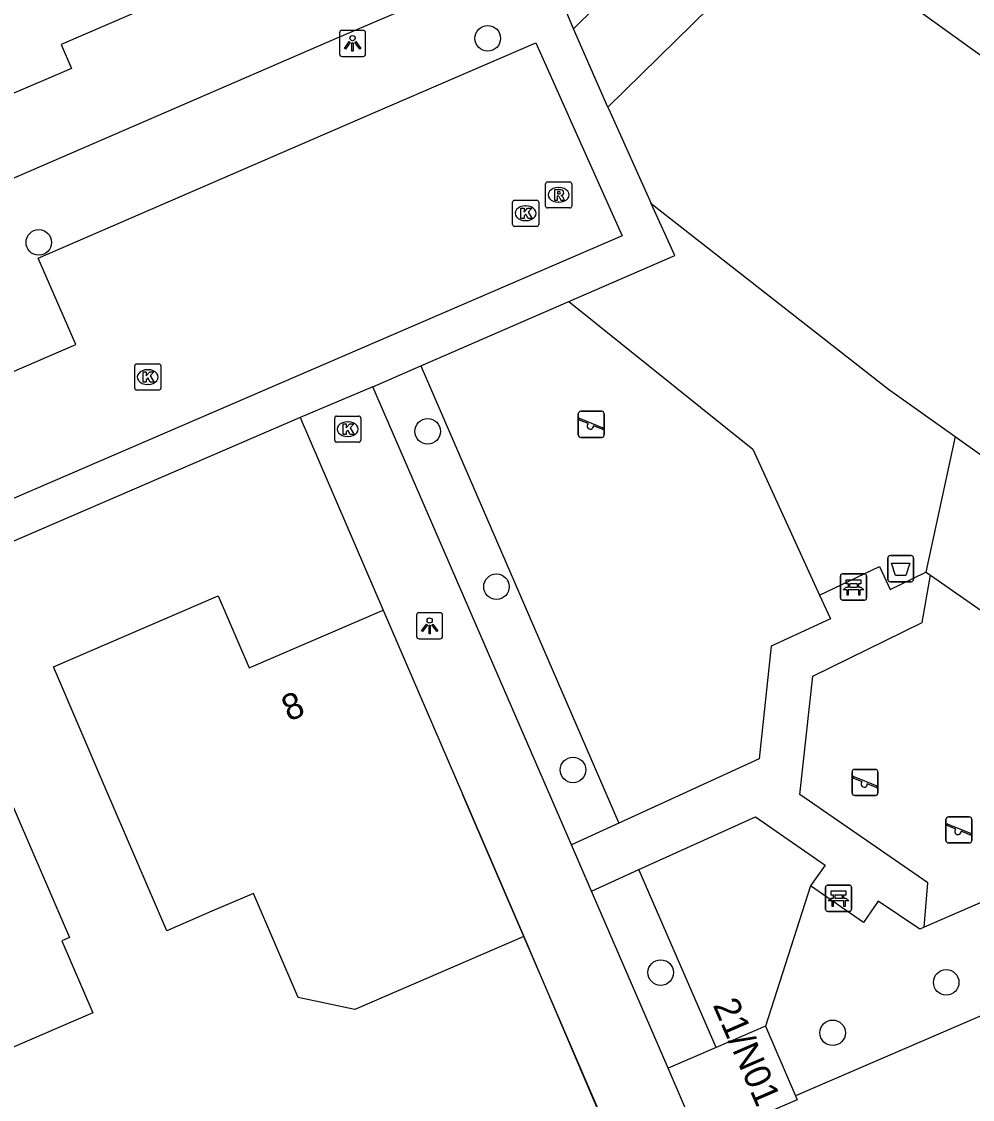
# Model space of a CAD drawing. Extents: x 157767 to 159171, y 387842 to 389425.
# Drawn here: x 158188.84 to 158225.26, y 388712.22 to 388753.46 of the extents above; entities that cross this region are included whole.
import ezdxf

# ---------------------------------------------------------------- set-up
doc = ezdxf.new("R2010")
doc.units = 0
for name, color, linetype in [('IMGEO_Afvalbak', 7, 'Continuous'), ('IMGEO_Bank', 7, 'Continuous'), ('IMGEO_Boom', 7, 'Continuous'), ('IMGEO_Groenvoorziening', 7, 'Continuous'), ('IMGEO_Kolk', 7, 'Continuous'), ('IMGEO_Lichtpunt', 7, 'Continuous'), ('IMGEO_Muur', 7, 'Continuous'), ('IMGEO_Pand', 7, 'Continuous'), ('IMGEO_Pand_nummerreeks', 7, 'Continuous'), ('IMGEO_Rijbaan_lokaal_open', 7, 'Continuous'), ('IMGEO_Rioolput', 7, 'Continuous'), ('IMGEO_Speelvoorziening', 7, 'Continuous'), ('IMGEO_Voetpad_open', 7, 'Continuous')]:
    doc.layers.add(name, color=color, linetype=linetype)

msp = doc.modelspace()

# ---------------------------------------------------------------- linework, layer by layer
at = {"layer": 'IMGEO_Afvalbak'}
for p, q in [((158222.016, 388732.127), (158222.016, 388732.927)), ((158222.016, 388732.927), (158222.016, 388732.127)), ((158222.116, 388733.027), (158222.906, 388733.027)), ((158222.906, 388733.027), (158222.116, 388733.027)), ((158223.006, 388732.927), (158223.006, 388732.127)), ((158223.006, 388732.127), (158223.006, 388732.927)), ((158222.906, 388732.027), (158222.116, 388732.027)), ((158222.116, 388732.027), (158222.906, 388732.027))]:
    msp.add_line(p, q, dxfattribs=at)
msp.add_lwpolyline([(158222.159, 388732.741), (158222.863, 388732.741), (158222.714, 388732.271), (158222.308, 388732.271), (158222.159, 388732.741)], dxfattribs=at)
for centre, start, end in [((158222.116, 388732.927), 90, 180), ((158222.116, 388732.927), 90, 180), ((158222.906, 388732.927), 0, 90), ((158222.906, 388732.927), 360, 90), ((158222.116, 388732.127), 180, 270), ((158222.116, 388732.127), 180, 270), ((158222.906, 388732.127), 270, 0), ((158222.906, 388732.127), 270, 0)]:
    msp.add_arc(centre, 0.1, start, end, dxfattribs=at)
at = {"layer": 'IMGEO_Bank'}
for p, q in [((158220.204, 388731.4), (158220.204, 388732.241)), ((158220.204, 388732.241), (158220.204, 388731.4)), ((158220.279, 388732.325), (158221.12, 388732.325)), ((158221.12, 388732.325), (158220.279, 388732.325)), ((158221.204, 388732.25), (158221.204, 388731.409)), ((158221.204, 388731.409), (158221.204, 388732.25)), ((158220.901, 388731.723), (158220.508, 388731.723)), ((158220.513, 388731.831), (158220.513, 388731.937)), ((158220.557, 388731.937), (158220.557, 388731.831)), ((158220.845, 388731.943), (158220.563, 388731.943)), ((158220.563, 388731.825), (158220.845, 388731.825)), ((158220.851, 388731.831), (158220.851, 388731.937)), ((158220.895, 388731.937), (158220.895, 388731.831)), ((158221.129, 388731.325), (158220.288, 388731.325)), ((158220.288, 388731.325), (158221.129, 388731.325)), ((158219.632, 388719.489), (158219.632, 388720.33)), ((158219.632, 388720.33), (158219.632, 388719.489)), ((158219.707, 388720.414), (158220.548, 388720.414)), ((158220.548, 388720.414), (158219.707, 388720.414)), ((158220.632, 388720.339), (158220.632, 388719.498)), ((158220.632, 388719.498), (158220.632, 388720.339)), ((158220.329, 388719.812), (158219.936, 388719.812)), ((158219.941, 388719.92), (158219.941, 388720.026)), ((158219.985, 388720.026), (158219.985, 388719.92)), ((158220.273, 388720.032), (158219.991, 388720.032)), ((158219.991, 388719.914), (158220.273, 388719.914)), ((158220.279, 388719.92), (158220.279, 388720.026)), ((158220.323, 388720.026), (158220.323, 388719.92)), ((158220.557, 388719.414), (158219.716, 388719.414)), ((158219.716, 388719.414), (158220.557, 388719.414))]:
    msp.add_line(p, q, dxfattribs=at)
for points in [[(158220.507, 388731.943), (158220.421, 388731.943), (158220.421, 388732.104), (158220.984, 388732.104), (158220.984, 388731.943), (158220.901, 388731.943)], [(158220.451, 388731.723), (158220.309, 388731.723), (158220.421, 388731.825), (158220.507, 388731.825)], [(158220.501, 388731.716), (158220.501, 388731.509), (158220.458, 388731.509), (158220.458, 388731.716)], [(158220.901, 388731.825), (158220.984, 388731.825), (158221.096, 388731.723), (158220.957, 388731.723)], [(158220.951, 388731.716), (158220.951, 388731.509), (158220.907, 388731.509), (158220.907, 388731.716)], [(158219.935, 388720.032), (158219.849, 388720.032), (158219.849, 388720.193), (158220.412, 388720.193), (158220.412, 388720.032), (158220.329, 388720.032)], [(158219.879, 388719.812), (158219.737, 388719.812), (158219.849, 388719.914), (158219.935, 388719.914)], [(158219.929, 388719.805), (158219.929, 388719.598), (158219.886, 388719.598), (158219.886, 388719.805)], [(158220.329, 388719.914), (158220.412, 388719.914), (158220.524, 388719.812), (158220.385, 388719.812)], [(158220.379, 388719.805), (158220.379, 388719.598), (158220.335, 388719.598), (158220.335, 388719.805)]]:
    msp.add_lwpolyline(points, dxfattribs=at)
for centre, radius, start, end in [((158220.282, 388732.247), 0.0779, 92.4484, 184.2845), ((158220.282, 388732.247), 0.0779, 92.4484, 184.2845), ((158221.126, 388732.247), 0.0779, 2.4484, 94.2845), ((158221.126, 388732.247), 0.0779, 2.4484, 94.2845), ((158220.451, 388731.716), 0.00671, 2.8957, 87.1043), ((158220.508, 388731.716), 0.00671, 92.8957, 177.1043), ((158220.506, 388731.936), 0.00671, 2.8957, 87.1043), ((158220.506, 388731.832), 0.00671, 272.8957, 357.1043), ((158220.563, 388731.936), 0.00671, 92.8957, 177.1043), ((158220.563, 388731.832), 0.00671, 182.8957, 267.1043), ((158220.845, 388731.936), 0.00671, 2.8957, 87.1043), ((158220.845, 388731.832), 0.00671, 272.8957, 357.1043), ((158220.902, 388731.936), 0.00671, 92.8957, 177.1043), ((158220.902, 388731.832), 0.00671, 182.8957, 267.1043), ((158220.9, 388731.716), 0.00671, 2.8957, 87.1043), ((158220.957, 388731.716), 0.00671, 92.8957, 177.1043), ((158220.282, 388731.403), 0.0779, 182.4484, 274.2845), ((158220.282, 388731.403), 0.0779, 182.4484, 274.2845), ((158221.126, 388731.403), 0.0779, 272.4484, 4.2845), ((158221.126, 388731.403), 0.0779, 272.4484, 4.2845), ((158219.71, 388720.336), 0.0779, 92.4484, 184.2845), ((158219.71, 388720.336), 0.0779, 92.4484, 184.2845), ((158220.554, 388720.336), 0.0779, 2.4484, 94.2845), ((158220.554, 388720.336), 0.0779, 2.4484, 94.2845), ((158219.879, 388719.805), 0.00671, 2.8957, 87.1043), ((158219.936, 388719.805), 0.00671, 92.8957, 177.1043), ((158219.934, 388720.025), 0.00671, 2.8957, 87.1043), ((158219.934, 388719.921), 0.00671, 272.8957, 357.1043), ((158219.991, 388720.025), 0.00671, 92.8957, 177.1043), ((158219.991, 388719.921), 0.00671, 182.8957, 267.1043), ((158220.273, 388720.025), 0.00671, 2.8957, 87.1043), ((158220.273, 388719.921), 0.00671, 272.8957, 357.1043), ((158220.33, 388720.025), 0.00671, 92.8957, 177.1043), ((158220.33, 388719.921), 0.00671, 182.8957, 267.1043), ((158220.328, 388719.805), 0.00671, 2.8957, 87.1043), ((158220.385, 388719.805), 0.00671, 92.8957, 177.1043), ((158219.71, 388719.492), 0.0779, 182.4484, 274.2845), ((158219.71, 388719.492), 0.0779, 182.4484, 274.2845), ((158220.554, 388719.492), 0.0779, 272.4484, 4.2845), ((158220.554, 388719.492), 0.0779, 272.4484, 4.2845)]:
    msp.add_arc(centre, radius, start, end, dxfattribs=at)
at = {"layer": 'IMGEO_Boom'}
for centre in [(158206.697, 388752.822), (158189.504, 388745.012), (158204.397, 388737.783), (158207.03, 388731.836), (158209.962, 388724.825), (158213.321, 388717.071), (158224.255, 388716.695), (158219.903, 388714.766)]:
    msp.add_circle(centre, 0.489, dxfattribs=at)
at = {"layer": 'IMGEO_Groenvoorziening'}
for points in [[(158212.961, 388746.496), (158222.043, 388739.397), (158224.591, 388737.583)], [(158209.8, 388742.746), (158216.855, 388737.107), (158219.408, 388731.518)], [(158204.129, 388740.284), (158211.717, 388722.785)], [(158224.591, 388737.583), (158223.475, 388732.398)], [(158224.591, 388737.583), (158233.388, 388731.323)], [(158223.652, 388732.275), (158230.525, 388727.497)], [(158233.388, 388731.323), (158243.682, 388723.997), (158242.224, 388722.582), (158218.48, 388712.357)], [(158230.525, 388727.497), (158229.878, 388721.619), (158223.408, 388718.812)], [(158215.439, 388714.205), (158212.486, 388721.014)], [(158219.055, 388720.384), (158217.333, 388715.021)]]:
    msp.add_lwpolyline(points, dxfattribs=at)
at = {"layer": 'IMGEO_Kolk'}
for p, q in [((158207.648, 388745.701), (158207.648, 388746.553)), ((158207.723, 388746.627), (158208.575, 388746.627)), ((158208.649, 388746.553), (158208.649, 388745.701)), ((158208.136, 388746.407), (158208.161, 388746.407)), ((158208.159, 388745.847), (158208.134, 388745.847)), ((158208.575, 388745.627), (158207.723, 388745.627)), ((158193.251, 388740.361), (158194.103, 388740.361)), ((158193.176, 388739.435), (158193.176, 388740.287)), ((158193.664, 388740.141), (158193.689, 388740.141)), ((158194.177, 388740.287), (158194.177, 388739.435)), ((158193.687, 388739.581), (158193.662, 388739.581)), ((158194.103, 388739.361), (158193.251, 388739.361)), ((158200.835, 388737.441), (158200.835, 388738.293)), ((158200.91, 388738.367), (158201.762, 388738.367)), ((158201.836, 388738.293), (158201.836, 388737.441)), ((158201.323, 388738.147), (158201.348, 388738.147)), ((158201.346, 388737.587), (158201.321, 388737.587)), ((158201.762, 388737.367), (158200.91, 388737.367))]:
    msp.add_line(p, q, dxfattribs=at)
for points in [[(158207.648, 388745.701), (158207.648, 388746.553)], [(158207.723, 388746.627), (158208.575, 388746.627)], [(158208.649, 388746.553), (158208.649, 388745.701)], [(158207.969, 388746.327), (158208.092, 388746.327), (158208.092, 388746.176), (158208.222, 388746.327), (158208.386, 388746.327), (158208.24, 388746.176), (158208.393, 388745.927), (158208.241, 388745.927), (158208.156, 388746.091), (158208.092, 388746.024), (158208.092, 388745.927), (158207.969, 388745.927), (158207.969, 388746.327)], [(158208.575, 388745.627), (158207.723, 388745.627)], [(158193.251, 388740.361), (158194.103, 388740.361)], [(158193.176, 388739.435), (158193.176, 388740.287)], [(158193.497, 388740.061), (158193.62, 388740.061), (158193.62, 388739.91), (158193.75, 388740.061), (158193.914, 388740.061), (158193.768, 388739.91), (158193.921, 388739.661), (158193.769, 388739.661), (158193.684, 388739.825), (158193.62, 388739.758), (158193.62, 388739.661), (158193.497, 388739.661), (158193.497, 388740.061)], [(158194.177, 388740.287), (158194.177, 388739.435)], [(158194.103, 388739.361), (158193.251, 388739.361)], [(158200.835, 388737.441), (158200.835, 388738.293)], [(158200.91, 388738.367), (158201.762, 388738.367)], [(158201.836, 388738.293), (158201.836, 388737.441)], [(158201.156, 388738.067), (158201.279, 388738.067), (158201.279, 388737.916), (158201.409, 388738.067), (158201.573, 388738.067), (158201.427, 388737.916), (158201.58, 388737.667), (158201.428, 388737.667), (158201.343, 388737.831), (158201.279, 388737.764), (158201.279, 388737.667), (158201.156, 388737.667), (158201.156, 388738.067)], [(158201.762, 388737.367), (158200.91, 388737.367)]]:
    msp.add_lwpolyline(points, dxfattribs=at)
for centre, start, end in [((158207.725, 388746.551), 91.552, 178.448), ((158207.725, 388746.551), 91.552, 178.448), ((158208.573, 388746.551), 1.552, 88.448), ((158208.573, 388746.551), 1.552, 88.448), ((158207.725, 388745.703), 181.552, 268.448), ((158207.725, 388745.703), 181.552, 268.448), ((158208.573, 388745.703), 271.552, 358.448), ((158208.573, 388745.703), 271.552, 358.448), ((158193.253, 388740.285), 91.552, 178.448), ((158193.253, 388740.285), 91.552, 178.448), ((158194.101, 388740.285), 1.552, 88.448), ((158194.101, 388740.285), 1.552, 88.448), ((158193.253, 388739.437), 181.552, 268.448), ((158193.253, 388739.437), 181.552, 268.448), ((158194.101, 388739.437), 271.552, 358.448), ((158194.101, 388739.437), 271.552, 358.448), ((158200.912, 388738.291), 91.552, 178.448), ((158200.912, 388738.291), 91.552, 178.448), ((158201.76, 388738.291), 1.552, 88.448), ((158201.76, 388738.291), 1.552, 88.448), ((158200.912, 388737.443), 181.552, 268.448), ((158200.912, 388737.443), 181.552, 268.448), ((158201.76, 388737.443), 271.552, 358.448), ((158201.76, 388737.443), 271.552, 358.448)]:
    msp.add_arc(centre, 0.0765, start, end, dxfattribs=at)
for centre, major_axis, ratio, start_param, end_param in [((158208.135, 388746.127), (-0.387, 0.002), 0.722429, 4.712389, 7.853982), ((158208.16, 388746.127), (-0.39, 0.002), 0.717154, 1.570796, 4.712389), ((158193.663, 388739.861), (-0.387, 0.002), 0.722429, 4.712389, 7.853982), ((158193.688, 388739.861), (-0.39, 0.002), 0.717154, 1.570796, 4.712389), ((158201.322, 388737.867), (-0.387, 0.002), 0.722429, 4.712389, 7.853982), ((158201.347, 388737.867), (-0.39, 0.002), 0.717154, 1.570796, 4.712389)]:
    msp.add_ellipse(centre, major_axis=major_axis, ratio=ratio, start_param=start_param, end_param=end_param, dxfattribs=at)
at = {"layer": 'IMGEO_Lichtpunt'}
for p, q in [((158201.922, 388753.128), (158201.114, 388753.128)), ((158201.922, 388753.128), (158201.114, 388753.128)), ((158201.02, 388753.033), (158201.02, 388752.226)), ((158201.02, 388753.033), (158201.02, 388752.226)), ((158202.016, 388752.226), (158202.016, 388753.033)), ((158202.016, 388752.226), (158202.016, 388753.033)), ((158201.114, 388752.132), (158201.922, 388752.132)), ((158201.114, 388752.132), (158201.922, 388752.132)), ((158204.875, 388730.841), (158204.067, 388730.841)), ((158204.875, 388730.841), (158204.067, 388730.841)), ((158203.973, 388730.746), (158203.973, 388729.939)), ((158203.973, 388730.746), (158203.973, 388729.939)), ((158204.969, 388729.939), (158204.969, 388730.746)), ((158204.969, 388729.939), (158204.969, 388730.746)), ((158204.067, 388729.845), (158204.875, 388729.845)), ((158204.067, 388729.845), (158204.875, 388729.845))]:
    msp.add_line(p, q, dxfattribs=at)
for points in [[(158201.394, 388752.697), (158201.433, 388752.669), (158201.245, 388752.407), (158201.207, 388752.434), (158201.394, 388752.697)], [(158201.496, 388752.649), (158201.543, 388752.649), (158201.543, 388752.327), (158201.496, 388752.327), (158201.496, 388752.649)], [(158201.606, 388752.669), (158201.644, 388752.696), (158201.831, 388752.434), (158201.792, 388752.406), (158201.606, 388752.669)], [(158204.347, 388730.41), (158204.386, 388730.382), (158204.198, 388730.12), (158204.16, 388730.147), (158204.347, 388730.41)], [(158204.449, 388730.362), (158204.496, 388730.362), (158204.496, 388730.04), (158204.449, 388730.04), (158204.449, 388730.362)], [(158204.559, 388730.382), (158204.597, 388730.409), (158204.784, 388730.147), (158204.745, 388730.119), (158204.559, 388730.382)]]:
    msp.add_lwpolyline(points, dxfattribs=at)
for centre in [(158201.519, 388752.831), (158204.472, 388730.544)]:
    msp.add_circle(centre, 0.0994, dxfattribs=at)
for centre, start, end in [((158201.114, 388753.033), 90, 180), ((158201.114, 388753.033), 90, 180), ((158201.922, 388753.033), 0, 90), ((158201.922, 388753.033), 0, 90), ((158201.114, 388752.226), 180, 270), ((158201.114, 388752.226), 180, 270), ((158201.922, 388752.226), 270, 0), ((158201.922, 388752.226), 270, 360), ((158204.067, 388730.746), 90, 180), ((158204.067, 388730.746), 90, 180), ((158204.875, 388730.746), 0, 90), ((158204.875, 388730.746), 0, 90), ((158204.067, 388729.939), 180, 270), ((158204.067, 388729.939), 180, 270), ((158204.875, 388729.939), 270, 0), ((158204.875, 388729.939), 270, 360)]:
    msp.add_arc(centre, 0.0946, start, end, dxfattribs=at)
at = {"layer": 'IMGEO_Muur'}
msp.add_lwpolyline([(158219.492, 388691.965), (158208.082, 388718.445), (158205.742, 388723.876)], dxfattribs=at)
at = {"layer": 'IMGEO_Pand'}
for points in [[(158185.06, 388764.409), (158190.755, 388766.862), (158194.764, 388761.425), (158197.732, 388757.4), (158193.263, 388755.469), (158193.856, 388754.097), (158190.364, 388752.593), (158190.76, 388751.674), (158188.28, 388750.606), (158187.884, 388751.524), (158186.507, 388750.931), (158184.529, 388755.523), (158182.754, 388759.647), (158180.658, 388758.744), (158178.898, 388762.855), (158184.666, 388765.325), (158185.06, 388764.409)], [(158230.196, 388750.586), (158229.778, 388750), (158228.799, 388748.625), (158228.677, 388748.712), (158226.872, 388750), (158226.022, 388750.606), (158226.604, 388751.421), (158221.686, 388754.973), (158221.107, 388754.172), (158217.789, 388756.568)], [(158208.082, 388718.445), (158201.61, 388715.654), (158199.433, 388716.121), (158197.722, 388720.099), (158196.136, 388719.417), (158194.406, 388718.672), (158192.038, 388724.176), (158190.062, 388728.768), (158196.37, 388731.488), (158197.56, 388728.729), (158202.694, 388730.943)], [(158202.694, 388730.943), (158205.742, 388723.876), (158208.082, 388718.445)], [(158186.531, 388713.361), (158185.717, 388713.645), (158184.761, 388715.865), (158184.222, 388715.633), (158184.064, 388715.999), (158180.256, 388714.358), (158180.611, 388713.534), (158180.336, 388713.416), (158178.45, 388717.794), (158176.472, 388722.385), (158180.924, 388724.305), (158181.118, 388723.851), (158183.711, 388724.946), (158183.315, 388725.864), (158186.817, 388727.374), (158188.794, 388722.782), (158190.675, 388718.413), (158190.382, 388718.287), (158191.569, 388715.532), (158186.531, 388713.361)], [(158217.333, 388715.021), (158215.439, 388714.205)], [(158217.333, 388715.021), (158218.48, 388712.357)], [(158215.439, 388714.205), (158213.602, 388713.414)], [(158214.816, 388710.595), (158213.602, 388713.414)], [(158218.48, 388712.357), (158218.547, 388712.202), (158214.816, 388710.595)]]:
    msp.add_lwpolyline(points, dxfattribs=at)
at = {"layer": 'IMGEO_Rijbaan_lokaal_open'}
msp.add_lwpolyline([(158169.237, 388731.746), (158190.927, 388741.104), (158189.483, 388744.405), (158202.38, 388750), (158208.536, 388752.656), (158209.72, 388750), (158209.916, 388749.563), (158211.85, 388745.262), (158145.024, 388716.464)], dxfattribs=at)
at = {"layer": 'IMGEO_Rioolput'}
for p, q in [((158208.91, 388746.404), (158208.91, 388747.256)), ((158208.985, 388747.33), (158209.837, 388747.33)), ((158209.398, 388747.11), (158209.423, 388747.11)), ((158209.911, 388747.256), (158209.911, 388746.404)), ((158209.421, 388746.55), (158209.396, 388746.55)), ((158209.837, 388746.33), (158208.985, 388746.33))]:
    msp.add_line(p, q, dxfattribs=at)
for points in [[(158208.91, 388746.404), (158208.91, 388747.256)], [(158208.985, 388747.33), (158209.837, 388747.33)], [(158209.499, 388747.028), (158209.247, 388747.03), (158209.247, 388746.63)], [(158209.425, 388746.949), (158209.371, 388746.949), (158209.371, 388746.868)], [(158209.911, 388747.256), (158209.911, 388746.404)], [(158209.247, 388746.63), (158209.371, 388746.63), (158209.371, 388746.792), (158209.382, 388746.792)], [(158209.371, 388746.868), (158209.423, 388746.868)], [(158209.429, 388746.763), (158209.5, 388746.63), (158209.64, 388746.63), (158209.575, 388746.756)], [(158209.837, 388746.33), (158208.985, 388746.33)]]:
    msp.add_lwpolyline(points, dxfattribs=at)
for centre, radius, start, end in [((158208.987, 388747.254), 0.0765, 91.552, 178.448), ((158208.987, 388747.254), 0.0765, 91.552, 178.448), ((158209.431, 388746.853), 0.0964, 77.0061, 93.1865), ((158209.445, 388746.91), 0.0378, 276.6634, 79.6772), ((158209.498, 388746.918), 0.109, 350.3612, 89.416), ((158209.835, 388747.254), 0.0765, 1.552, 88.448), ((158209.835, 388747.254), 0.0765, 1.552, 88.448), ((158209.381, 388746.739), 0.0533, 26.0293, 88.6989), ((158209.407, 388747.057), 0.19, 274.7715, 282.9687), ((158209.496, 388746.918), 0.112, 277.5842, 350.9817), ((158209.48, 388746.703), 0.108, 29.5134, 73.7905), ((158208.987, 388746.406), 0.0765, 181.552, 268.448), ((158208.987, 388746.406), 0.0765, 181.552, 268.448), ((158209.835, 388746.406), 0.0765, 271.552, 358.448), ((158209.835, 388746.406), 0.0765, 271.552, 358.448)]:
    msp.add_arc(centre, radius, start, end, dxfattribs=at)
for centre, major_axis, ratio, start_param, end_param in [((158209.397, 388746.83), (-0.387, 0.002), 0.722429, 4.712389, 7.853982), ((158209.422, 388746.83), (-0.39, 0.002), 0.717154, 1.570796, 4.712389)]:
    msp.add_ellipse(centre, major_axis=major_axis, ratio=ratio, start_param=start_param, end_param=end_param, dxfattribs=at)
at = {"layer": 'IMGEO_Speelvoorziening'}
for p, q in [((158210.164, 388737.649), (158210.164, 388738.449)), ((158210.164, 388738.449), (158210.164, 388737.649)), ((158210.233, 388738.274), (158211.109, 388737.921)), ((158210.264, 388738.549), (158211.054, 388738.549)), ((158211.054, 388738.549), (158210.264, 388738.549)), ((158211.154, 388738.449), (158211.154, 388737.649)), ((158211.154, 388737.649), (158211.154, 388738.449)), ((158210.547, 388738.077), (158210.208, 388738.214)), ((158211.085, 388737.861), (158210.745, 388737.998)), ((158211.054, 388737.549), (158210.264, 388737.549)), ((158210.264, 388737.549), (158211.054, 388737.549)), ((158220.65, 388723.946), (158220.65, 388724.746)), ((158220.65, 388724.746), (158220.65, 388723.946)), ((158220.75, 388724.846), (158221.54, 388724.846)), ((158221.54, 388724.846), (158220.75, 388724.846)), ((158221.64, 388724.746), (158221.64, 388723.946)), ((158221.64, 388723.946), (158221.64, 388724.746)), ((158221.033, 388724.374), (158220.694, 388724.511)), ((158220.719, 388724.571), (158221.595, 388724.218)), ((158221.571, 388724.158), (158221.231, 388724.295)), ((158221.54, 388723.846), (158220.75, 388723.846)), ((158220.75, 388723.846), (158221.54, 388723.846)), ((158224.343, 388723.031), (158225.133, 388723.031)), ((158225.133, 388723.031), (158224.343, 388723.031)), ((158224.243, 388722.131), (158224.243, 388722.931)), ((158224.243, 388722.931), (158224.243, 388722.131)), ((158224.626, 388722.559), (158224.287, 388722.696)), ((158224.312, 388722.756), (158225.188, 388722.403)), ((158225.233, 388722.931), (158225.233, 388722.131)), ((158225.233, 388722.131), (158225.233, 388722.931)), ((158225.164, 388722.343), (158224.824, 388722.48)), ((158225.133, 388722.031), (158224.343, 388722.031)), ((158224.343, 388722.031), (158225.133, 388722.031))]:
    msp.add_line(p, q, dxfattribs=at)
for centre, radius, start, end in [((158210.264, 388738.449), 0.1, 90, 180), ((158210.264, 388738.449), 0.1, 90, 180), ((158210.221, 388738.244), 0.0327, 68.078, 248.078), ((158211.054, 388738.449), 0.1, 0, 90), ((158211.054, 388738.449), 0.1, 360, 90), ((158210.626, 388737.987), 0.12, 130.9928, 5.1632), ((158211.097, 388737.891), 0.0327, 248.078, 68.078), ((158210.264, 388737.649), 0.1, 180, 270), ((158210.264, 388737.649), 0.1, 180, 270), ((158211.054, 388737.649), 0.1, 270, 0), ((158211.054, 388737.649), 0.1, 270, 0), ((158220.75, 388724.746), 0.1, 90, 180), ((158220.75, 388724.746), 0.1, 90, 180), ((158221.54, 388724.746), 0.1, 0, 90), ((158221.54, 388724.746), 0.1, 360, 90), ((158220.707, 388724.541), 0.0327, 68.078, 248.078), ((158221.112, 388724.284), 0.12, 130.9928, 5.1632), ((158220.75, 388723.946), 0.1, 180, 270), ((158220.75, 388723.946), 0.1, 180, 270), ((158221.54, 388723.946), 0.1, 270, 0), ((158221.54, 388723.946), 0.1, 270, 0), ((158221.583, 388724.188), 0.0327, 248.078, 68.078), ((158224.343, 388722.931), 0.1, 90, 180), ((158224.343, 388722.931), 0.1, 90, 180), ((158225.133, 388722.931), 0.1, 0, 90), ((158225.133, 388722.931), 0.1, 360, 90), ((158224.3, 388722.726), 0.0327, 68.078, 248.078), ((158224.705, 388722.469), 0.12, 130.9928, 5.1632), ((158225.176, 388722.373), 0.0327, 248.078, 68.078), ((158224.343, 388722.131), 0.1, 180, 270), ((158224.343, 388722.131), 0.1, 180, 270), ((158225.133, 388722.131), 0.1, 270, 0), ((158225.133, 388722.131), 0.1, 270, 0)]:
    msp.add_arc(centre, radius, start, end, dxfattribs=at)
at = {"layer": 'IMGEO_Voetpad_open'}
for points in [[(158215.981, 388759.107), (158209.98, 388753.187)], [(158217.789, 388756.568), (158211.294, 388750.191)], [(158209.98, 388753.187), (158208.741, 388756.173), (158200.983, 388752.851), (158194.387, 388750), (158185.972, 388746.363), (158187.619, 388742.643), (158165.563, 388733.146)], [(158211.294, 388750.191), (158209.98, 388753.187)], [(158211.294, 388750.191), (158211.38, 388750), (158212.961, 388746.496)], [(158209.8, 388742.746), (158213.858, 388744.508), (158212.961, 388746.496)], [(158204.129, 388740.284), (158209.8, 388742.746)], [(158202.295, 388739.488), (158204.129, 388740.284)], [(158202.295, 388739.488), (158199.515, 388738.309)], [(158209.899, 388721.953), (158202.295, 388739.488)], [(158199.515, 388738.309), (158146.245, 388715.336)], [(158199.515, 388738.309), (158202.694, 388730.943)], [(158219.408, 388731.518), (158221.699, 388732.607), (158222.111, 388731.735), (158223.475, 388732.398)], [(158223.408, 388718.812), (158223.545, 388720.509), (158218.652, 388723.882), (158219.148, 388728.417), (158223.335, 388730.472), (158223.652, 388732.275)], [(158223.475, 388732.398), (158223.652, 388732.275)], [(158219.408, 388731.518), (158219.821, 388730.614), (158217.549, 388729.559), (158217.094, 388725.246), (158211.717, 388722.785)], [(158212.486, 388721.014), (158216.953, 388723.036), (158219.614, 388721.18), (158219.055, 388720.384)], [(158211.717, 388722.785), (158209.899, 388721.953)], [(158210.664, 388720.189), (158209.899, 388721.953)], [(158210.664, 388720.189), (158212.486, 388721.014)], [(158213.602, 388713.414), (158210.664, 388720.189)], [(158223.408, 388718.812), (158223.238, 388718.738), (158221.645, 388719.803), (158221.093, 388718.988), (158219.055, 388720.384)], [(158208.082, 388718.445), (158211.972, 388709.33)]]:
    msp.add_lwpolyline(points, dxfattribs=at)

# ---------------------------------------------------------------- texts
at = {"layer": 'IMGEO_Pand_nummerreeks'}
for s, rotation, p in [('8', 23.3278, (158199.082, 388726.663)), ('21/N01', 293.4481, (158215.306, 388715.829))]:
    msp.add_text(s, height=1, rotation=rotation, dxfattribs=at).set_placement(p)

doc.saveas('drawing.dxf')
